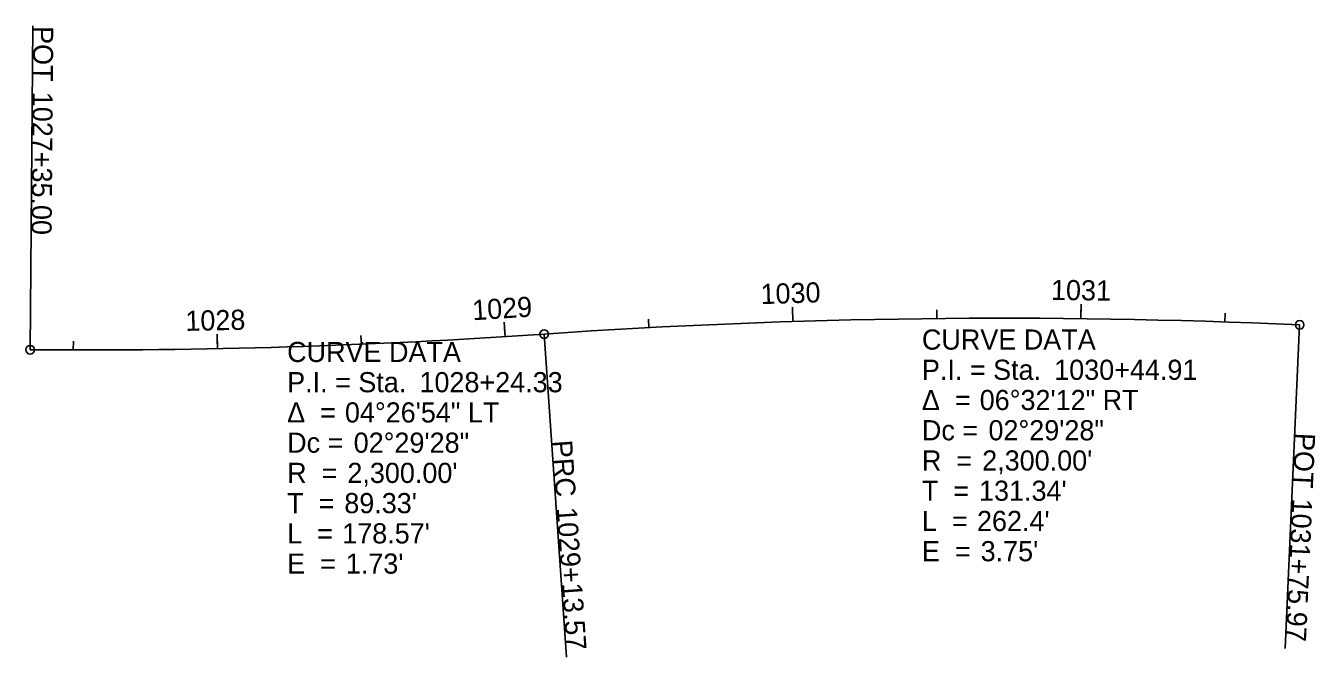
# Model space of a CAD drawing. Extents: x 2192763 to 2198189, y 660254 to 661868.
# Drawn here: x 2197741.3 to 2198188.9, y 661648.8 to 661868.1 of the extents above; entities that cross this region are included whole.
import ezdxf

# ---------------------------------------------------------------- set-up
doc = ezdxf.new("R2010")
doc.units = 0
for name, color, linetype in [('PM_X_Cells', 7, 'Continuous'), ('PM_X_CL_Double_Solid', 7, 'Continuous'), ('PM_X_Crosswalk', 7, 'Continuous'), ('PM_X_Dotted_Line', 7, 'Continuous'), ('PM_X_Edge_Line', 7, 'Continuous'), ('PM_X_Stop_Line', 7, 'Continuous'), ('PM_X_Yield_Line', 7, 'Continuous')]:
    doc.layers.add(name, color=color, linetype=linetype)

msp = doc.modelspace()

# ---------------------------------------------------------------- linework, layer by layer
at = {"layer": 'PM_X_Cells'}
for p, q in [((2197742.83, 661755.61), (2197743.78, 661868.11)), ((2198007.59, 661765.4), (2198007.43, 661770.4)), ((2197921.27, 661761.04), (2197929.06, 661648.81)), ((2198183.51, 661764.24), (2198178.47, 661651.86))]:
    msp.add_line(p, q, dxfattribs=at)
for centre in [(2198183.51, 661764.24), (2197921.27, 661761.04), (2197742.83, 661755.61)]:
    msp.add_circle(centre, 1.5, dxfattribs=at)
at = {"layer": 'PM_X_CL_Double_Solid'}
for p, q in [((2197742.83, 661755.61), (2197743.78, 661868.11)), ((2198007.59, 661765.4), (2198007.43, 661770.4)), ((2198107.58, 661766.39), (2198107.61, 661769.39)), ((2197907.74, 661760.14), (2197907.55, 661763.14)), ((2197921.27, 661761.04), (2197929.06, 661648.81)), ((2198183.51, 661764.24), (2198178.47, 661651.86)), ((2197807.83, 661755.98), (2197807.77, 661758.98))]:
    msp.add_line(p, q, dxfattribs=at)
for centre in [(2198183.51, 661764.24), (2197921.27, 661761.04), (2197742.83, 661755.61)]:
    msp.add_circle(centre, 1.5, dxfattribs=at)
at = {"layer": 'PM_X_Edge_Line'}
for centre, start, end in [((2198080.42, 659466.55), 87.43113, 93.96783), ((2197762.12, 664055.53), 269.51956, 273.96783)]:
    msp.add_arc(centre, 2300, start, end, dxfattribs=at)
at = {"layer": 'PM_X_Yield_Line'}
for p, q in [((2197742.83, 661755.61), (2197743.78, 661868.11)), ((2198007.59, 661765.4), (2198007.43, 661770.4)), ((2198057.58, 661766.44), (2198057.55, 661769.44)), ((2198107.58, 661766.39), (2198107.64, 661771.39)), ((2197907.74, 661760.14), (2197907.42, 661765.13)), ((2197957.64, 661763.28), (2197957.48, 661766.27)), ((2198157.57, 661765.26), (2198157.67, 661768.26)), ((2197807.83, 661755.98), (2197807.73, 661760.98)), ((2197857.81, 661757.52), (2197857.68, 661760.52)), ((2197921.27, 661761.04), (2197929.06, 661648.81)), ((2198183.51, 661764.24), (2198178.47, 661651.86)), ((2197757.83, 661755.53), (2197757.84, 661758.53))]:
    msp.add_line(p, q, dxfattribs=at)
for centre in [(2198183.51, 661764.24), (2197921.27, 661761.04), (2197742.83, 661755.61)]:
    msp.add_circle(centre, 1.5, dxfattribs=at)

# ---------------------------------------------------------------- texts
at = {"layer": 'PM_X_Cells'}
for s, rotation, p in [('POT', 269.5196, (2197743.89, 661868.02)), ('1027+35.00', 269.5196, (2197743.7, 661845.2)), ('1030', 1.8146, (2197996.48, 661771.42)), ('POT', 267.4311, (2198181.95, 661726.84)), ('PRC', 273.9678, (2197923.96, 661723.97)), ('1031+75.97', 267.4311, (2198180.93, 661704.04)), ('1029+13.57', 273.9678, (2197925.58, 661700.66))]:
    msp.add_text(s, height=7, rotation=rotation, dxfattribs=at).set_placement(p)
at = {"layer": 'PM_X_CL_Double_Solid'}
for s, rotation, p in [('POT', 269.5196, (2197743.89, 661868.02)), ('1027+35.00', 269.5196, (2197743.7, 661845.2)), ('1030', 1.8146, (2197996.48, 661771.42)), ('POT', 267.4311, (2198181.95, 661726.84)), ('PRC', 273.9678, (2197923.96, 661723.97)), ('1031+75.97', 267.4311, (2198180.93, 661704.04)), ('1029+13.57', 273.9678, (2197925.58, 661700.66))]:
    msp.add_text(s, height=7, rotation=rotation, dxfattribs=at).set_placement(p)
at = {"layer": 'PM_X_Crosswalk'}
for s, p in [('CURVE DATA', (2198052.39, 661755.64)), ('CURVE DATA', (2197832.05, 661751.33)), ('P.I. = Sta. ', (2198052.39, 661745.14)), ('1030+44.91', (2198098.31, 661745.14)), ('P.I. = Sta. ', (2197832.05, 661740.83)), ('1028+24.33', (2197877.98, 661740.83)), ('Δ  = ', (2198052.39, 661734.64)), ('06°32\'12" RT', (2198072.45, 661734.64)), ('Δ  = ', (2197832.05, 661730.33)), ('04°26\'54" LT', (2197852.11, 661730.33)), ('Dc = ', (2198052.39, 661724.14)), ('02°29\'28"', (2198075.49, 661724.14)), ('Dc = ', (2197832.05, 661719.83)), ('02°29\'28"', (2197855.15, 661719.83)), ('R  = ', (2198052.39, 661713.64)), ("2,300.00'", (2198073.31, 661713.64)), ('R  = ', (2197832.05, 661709.33)), ("2,300.00'", (2197852.97, 661709.33)), ('T  = ', (2198052.39, 661703.14)), ("131.34'", (2198072.22, 661703.14)), ('T  = ', (2197832.05, 661698.83)), ("89.33'", (2197851.89, 661698.83)), ('L  = ', (2198052.39, 661692.64)), ("262.4'", (2198071.51, 661692.64)), ('L  = ', (2197832.05, 661688.33)), ("178.57'", (2197851.17, 661688.33)), ('E  = ', (2198052.39, 661682.14)), ("3.75'", (2198072.77, 661682.14)), ('E  = ', (2197832.05, 661677.83)), ("1.73'", (2197852.43, 661677.83))]:
    msp.add_text(s, height=7, dxfattribs=at).set_placement(p)
at = {"layer": 'PM_X_Dotted_Line'}
for s, p in [('CURVE DATA', (2198052.39, 661755.64)), ('CURVE DATA', (2197832.05, 661751.33)), ('P.I. = Sta. ', (2198052.39, 661745.14)), ('1030+44.91', (2198098.31, 661745.14)), ('P.I. = Sta. ', (2197832.05, 661740.83)), ('1028+24.33', (2197877.98, 661740.83)), ('Δ  = ', (2198052.39, 661734.64)), ('06°32\'12" RT', (2198072.45, 661734.64)), ('Δ  = ', (2197832.05, 661730.33)), ('04°26\'54" LT', (2197852.11, 661730.33)), ('Dc = ', (2198052.39, 661724.14)), ('02°29\'28"', (2198075.49, 661724.14)), ('Dc = ', (2197832.05, 661719.83)), ('02°29\'28"', (2197855.15, 661719.83)), ('R  = ', (2198052.39, 661713.64)), ("2,300.00'", (2198073.31, 661713.64)), ('R  = ', (2197832.05, 661709.33)), ("2,300.00'", (2197852.97, 661709.33)), ('T  = ', (2198052.39, 661703.14)), ("131.34'", (2198072.22, 661703.14)), ('T  = ', (2197832.05, 661698.83)), ("89.33'", (2197851.89, 661698.83)), ('L  = ', (2198052.39, 661692.64)), ("262.4'", (2198071.51, 661692.64)), ('L  = ', (2197832.05, 661688.33)), ("178.57'", (2197851.17, 661688.33)), ('E  = ', (2198052.39, 661682.14)), ("3.75'", (2198072.77, 661682.14)), ('E  = ', (2197832.05, 661677.83)), ("1.73'", (2197852.43, 661677.83))]:
    msp.add_text(s, height=7, dxfattribs=at).set_placement(p)
at = {"layer": 'PM_X_Stop_Line'}
for s, p in [('CURVE DATA', (2198052.39, 661755.64)), ('CURVE DATA', (2197832.05, 661751.33)), ('P.I. = Sta. ', (2198052.39, 661745.14)), ('1030+44.91', (2198098.31, 661745.14)), ('P.I. = Sta. ', (2197832.05, 661740.83)), ('1028+24.33', (2197877.98, 661740.83)), ('Δ  = ', (2198052.39, 661734.64)), ('06°32\'12" RT', (2198072.45, 661734.64)), ('Δ  = ', (2197832.05, 661730.33)), ('04°26\'54" LT', (2197852.11, 661730.33)), ('Dc = ', (2198052.39, 661724.14)), ('02°29\'28"', (2198075.49, 661724.14)), ('Dc = ', (2197832.05, 661719.83)), ('02°29\'28"', (2197855.15, 661719.83)), ('R  = ', (2198052.39, 661713.64)), ("2,300.00'", (2198073.31, 661713.64)), ('R  = ', (2197832.05, 661709.33)), ("2,300.00'", (2197852.97, 661709.33)), ('T  = ', (2198052.39, 661703.14)), ("131.34'", (2198072.22, 661703.14)), ('T  = ', (2197832.05, 661698.83)), ("89.33'", (2197851.89, 661698.83)), ('L  = ', (2198052.39, 661692.64)), ("262.4'", (2198071.51, 661692.64)), ('L  = ', (2197832.05, 661688.33)), ("178.57'", (2197851.17, 661688.33)), ('E  = ', (2198052.39, 661682.14)), ("3.75'", (2198072.77, 661682.14)), ('E  = ', (2197832.05, 661677.83)), ("1.73'", (2197852.43, 661677.83))]:
    msp.add_text(s, height=7, dxfattribs=at).set_placement(p)
at = {"layer": 'PM_X_Yield_Line'}
for s, rotation, p in [('POT', 269.5196, (2197743.89, 661868.02)), ('1027+35.00', 269.5196, (2197743.7, 661845.2)), ('1030', 1.8146, (2197996.48, 661771.42)), ('1031', 359.3235, (2198097.16, 661772.89)), ('1029', 3.6299, (2197896.51, 661765.81)), ('1028', 1.1388, (2197796.79, 661762.13)), ('POT', 267.4311, (2198181.95, 661726.84)), ('PRC', 273.9678, (2197923.96, 661723.97)), ('1031+75.97', 267.4311, (2198180.93, 661704.04)), ('1029+13.57', 273.9678, (2197925.58, 661700.66))]:
    msp.add_text(s, height=7, rotation=rotation, dxfattribs=at).set_placement(p)

doc.saveas('drawing.dxf')
